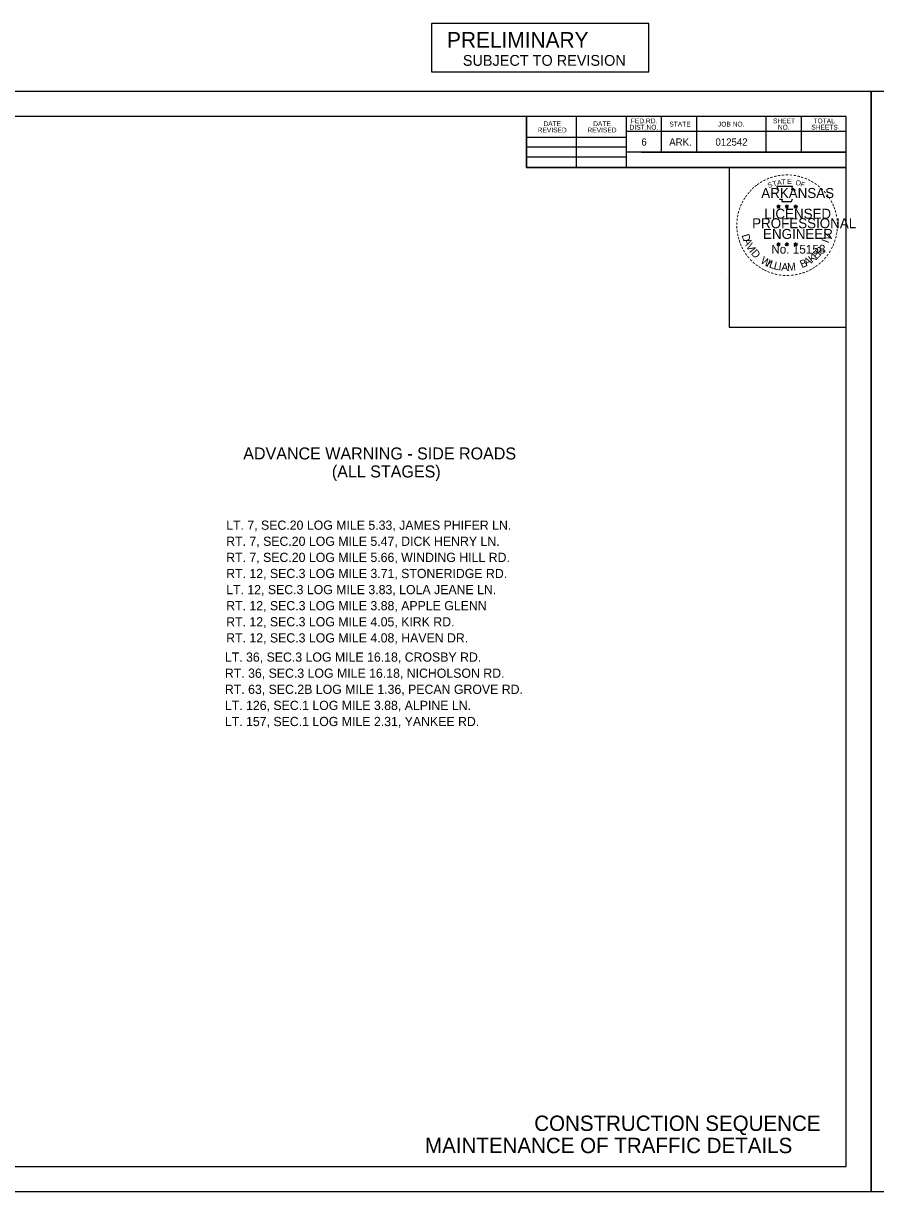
# Model space of a CAD drawing. Extents: x 32485 to 39285, y 55121 to 58033.
# Drawn here: x 33337 to 34190, y 56764 to 57932 of the extents above; entities that cross this region are included whole.
import ezdxf

# ---------------------------------------------------------------- set-up
doc = ezdxf.new("R2010")
doc.units = 0
for name, color, linetype in [('Default', 7, 'Continuous'), ('R_Border Notes', 7, 'Continuous'), ('R_Dimension', 7, 'Continuous'), ('SHET_Annotations', 7, 'Continuous'), ('SHET_Border-Lines', 7, 'Continuous'), ('SHET_Border-Text', 7, 'Continuous'), ('SHET_Stamp-PE-Chief-Eng', 7, 'Continuous'), ('SHET_Stamp-Seal', 7, 'Continuous')]:
    doc.layers.add(name, color=color, linetype=linetype)

msp = doc.modelspace()

# ---------------------------------------------------------------- linework, layer by layer
at = {"layer": 'Default'}
for points in [[(33745.4, 57883.5), (33962.8, 57883.5), (33962.8, 57932), (33745.4, 57932)], [(32485, 57863.9), (32485, 56763.9), (34185, 56763.9), (34185, 57863.9)], [(34185, 57863.9), (34185, 56763.9), (35885, 56763.9), (35885, 57863.9)]]:
    msp.add_lwpolyline(points, close=True, dxfattribs=at)
at = {"layer": 'R_Border Notes'}
for p, q in [((33840.5, 57788), (33840.5, 57838.9)), ((33890.4, 57788), (33890.4, 57838.9)), ((33940.2, 57838.9), (33940.2, 57788)), ((33975.1, 57838.9), (33975.1, 57803.1)), ((34010.5, 57838.9), (34010.5, 57803.1)), ((34079.7, 57838.9), (34079.7, 57803.1)), ((34115.1, 57838.9), (34115.1, 57803.1)), ((34160, 57823.8), (33940.2, 57823.8)), ((34160, 57823.9), (34160, 57823.9)), ((33840.5, 57818.2), (33940.2, 57818.2)), ((33840.5, 57808.6), (33940.2, 57808.6)), ((34160, 57803.1), (33940.2, 57803.1)), ((33955.3, 57803.1), (34160, 57803.1)), ((33840.5, 57798.6), (33940.2, 57798.6)), ((34160, 57788), (33840.5, 57788))]:
    msp.add_line(p, q, dxfattribs=at)
for points in [[(32485, 56763.9), (34185, 56763.9), (34185, 57863.9), (32485, 57863.9)], [(34185, 56763.9), (35885, 56763.9), (35885, 57863.9), (34185, 57863.9)], [(32510, 56788.9), (34160, 56788.9), (34160, 57838.9), (32510, 57838.9)], [(33840.5, 57788), (34160, 57788), (34160, 57838.9), (33840.5, 57838.9)]]:
    msp.add_lwpolyline(points, close=True, dxfattribs=at)
at = {"layer": 'R_Dimension'}
for p, q in [((34090.7, 57749.5), (34092.5, 57748.9)), ((34090.7, 57749.5), (34092, 57749.2)), ((34090.7, 57749.5), (34091.9, 57748.9)), ((34091.4, 57747.4), (34092.5, 57748.9)), ((34091.4, 57747.4), (34092, 57748.7)), ((34091.4, 57747.4), (34092.5, 57748.5)), ((34092.5, 57750.7), (34092.3, 57749.5)), ((34092.5, 57748.9), (34092.5, 57750.7)), ((34092.5, 57750.7), (34092.7, 57749.5)), ((34094.2, 57749.5), (34092.5, 57748.9)), ((34093.5, 57747.4), (34092.5, 57748.9)), ((34093.5, 57747.4), (34092.5, 57748.5)), ((34094.2, 57749.5), (34092.8, 57749.2)), ((34093.5, 57747.4), (34092.8, 57748.9)), ((34094.2, 57749.5), (34093.2, 57749)), ((34099.1, 57749.5), (34100.8, 57748.9)), ((34099.1, 57749.5), (34100.3, 57749.2)), ((34099.1, 57749.5), (34100.3, 57748.9)), ((34099.7, 57747.4), (34100.8, 57748.9)), ((34099.7, 57747.4), (34100.4, 57748.7)), ((34099.7, 57747.4), (34100.8, 57748.5)), ((34100.8, 57750.7), (34100.6, 57749.5)), ((34100.8, 57748.9), (34100.8, 57750.7)), ((34100.8, 57750.7), (34101.1, 57749.5)), ((34102.6, 57749.5), (34100.8, 57748.9)), ((34101.9, 57747.4), (34100.8, 57748.9)), ((34101.9, 57747.4), (34100.8, 57748.5)), ((34102.6, 57749.5), (34101.1, 57749.2)), ((34101.9, 57747.4), (34101.2, 57748.9)), ((34102.6, 57749.5), (34101.5, 57749)), ((34107.9, 57749.4), (34109.6, 57748.9)), ((34107.9, 57749.4), (34109.2, 57749.2)), ((34107.9, 57749.4), (34109.1, 57748.8)), ((34108.6, 57747.4), (34109.6, 57748.9)), ((34108.6, 57747.4), (34109.2, 57748.6)), ((34108.6, 57747.4), (34109.6, 57748.5)), ((34109.6, 57750.7), (34109.4, 57749.4)), ((34109.6, 57748.9), (34109.6, 57750.7)), ((34109.6, 57750.7), (34109.9, 57749.4)), ((34111.4, 57749.4), (34109.6, 57748.9)), ((34110.7, 57747.4), (34109.6, 57748.9)), ((34110.7, 57747.4), (34109.6, 57748.4)), ((34111.4, 57749.4), (34109.9, 57749.2)), ((34110.7, 57747.4), (34110, 57748.8)), ((34111.4, 57749.4), (34110.4, 57748.9)), ((34090.7, 57711.6), (34092.4, 57711.1)), ((34090.7, 57711.6), (34092, 57711.4)), ((34090.7, 57711.6), (34091.9, 57711)), ((34091.4, 57709.6), (34092.4, 57711.1)), ((34091.4, 57709.6), (34092, 57710.8)), ((34091.4, 57709.6), (34092.4, 57710.7)), ((34092.4, 57712.9), (34092.2, 57711.6)), ((34092.4, 57711.1), (34092.4, 57712.9)), ((34092.4, 57712.9), (34092.7, 57711.6)), ((34094.2, 57711.6), (34092.4, 57711.1)), ((34093.5, 57709.6), (34092.4, 57711.1)), ((34093.5, 57709.6), (34092.4, 57710.6)), ((34094.2, 57711.6), (34092.8, 57711.4)), ((34093.5, 57709.6), (34092.8, 57711)), ((34094.2, 57711.6), (34093.2, 57711.1)), ((34099, 57711.6), (34100.8, 57711.1)), ((34099, 57711.6), (34100.3, 57711.4)), ((34099, 57711.6), (34100.2, 57711)), ((34099.7, 57709.6), (34100.8, 57711.1)), ((34099.7, 57709.6), (34100.3, 57710.8)), ((34099.7, 57709.6), (34100.8, 57710.7)), ((34100.8, 57712.9), (34100.6, 57711.6)), ((34100.8, 57711.1), (34100.8, 57712.9)), ((34100.8, 57712.9), (34101, 57711.6)), ((34102.5, 57711.6), (34100.8, 57711.1)), ((34101.9, 57709.6), (34100.8, 57711.1)), ((34101.9, 57709.6), (34100.8, 57710.6)), ((34102.5, 57711.6), (34101.1, 57711.4)), ((34101.9, 57709.6), (34101.2, 57711)), ((34102.5, 57711.6), (34101.5, 57711.1)), ((34107.9, 57711.6), (34109.6, 57711)), ((34107.9, 57711.6), (34109.1, 57711.3)), ((34107.9, 57711.6), (34109.1, 57710.9)), ((34108.5, 57709.5), (34109.6, 57711)), ((34108.5, 57709.5), (34109.2, 57710.7)), ((34108.5, 57709.5), (34109.6, 57710.6)), ((34109.6, 57712.8), (34109.4, 57711.6)), ((34109.6, 57711), (34109.6, 57712.8)), ((34109.6, 57712.8), (34109.9, 57711.6)), ((34111.4, 57711.6), (34109.6, 57711)), ((34110.7, 57709.5), (34109.6, 57711)), ((34110.7, 57709.5), (34109.6, 57710.6)), ((34111.4, 57711.6), (34109.9, 57711.3)), ((34110.7, 57709.5), (34110, 57711)), ((34111.4, 57711.6), (34110.3, 57711))]:
    msp.add_line(p, q, dxfattribs=at)
for points in [[(34090.9, 57768.9), (34092.3, 57764.7)], [(34108.5, 57764.3), (34109.2, 57765.7), (34105.8, 57765.6), (34106.5, 57768.9), (34090.9, 57768.9)], [(34093.4, 57756.7), (34093.4, 57756.3), (34096.2, 57756.2), (34095.9, 57753.9), (34105.3, 57753.9), (34106.3, 57756.5)], [(34092.5, 57750.7), (34093.5, 57747.4), (34090.7, 57749.5), (34094.2, 57749.5), (34091.4, 57747.4), (34092.5, 57750.7)], [(34100.8, 57750.7), (34101.9, 57747.4), (34099.1, 57749.5), (34102.6, 57749.5), (34099.7, 57747.4), (34100.8, 57750.7)], [(34109.6, 57750.7), (34110.7, 57747.4), (34107.9, 57749.4), (34111.4, 57749.4), (34108.6, 57747.4), (34109.6, 57750.7)], [(34092.4, 57712.9), (34093.5, 57709.6), (34090.7, 57711.6), (34094.2, 57711.6), (34091.4, 57709.6), (34092.4, 57712.9)], [(34100.8, 57712.9), (34101.9, 57709.6), (34099, 57711.6), (34102.5, 57711.6), (34099.7, 57709.6), (34100.8, 57712.9)], [(34109.6, 57712.8), (34110.7, 57709.5), (34107.9, 57711.6), (34111.4, 57711.6), (34108.5, 57709.5), (34109.6, 57712.8)]]:
    msp.add_lwpolyline(points, dxfattribs=at)
for centre, radius in [((34092.5, 57748.9), 0.861), ((34092.5, 57748.9), 0.723), ((34092.5, 57748.9), 0.579), ((34092.5, 57748.9), 0.495), ((34092.5, 57748.9), 0.374), ((34092.5, 57748.9), 0.248), ((34092.5, 57748.9), 0.148), ((34100.8, 57748.9), 0.861), ((34100.8, 57748.9), 0.723), ((34100.8, 57748.9), 0.579), ((34100.8, 57748.9), 0.495), ((34100.8, 57748.9), 0.374), ((34100.8, 57748.9), 0.248), ((34100.8, 57748.9), 0.148), ((34109.6, 57748.9), 0.861), ((34109.6, 57748.9), 0.723), ((34109.6, 57748.9), 0.579), ((34109.6, 57748.9), 0.495), ((34109.6, 57748.9), 0.374), ((34109.6, 57748.9), 0.248), ((34109.6, 57748.9), 0.148), ((34092.4, 57711), 0.861), ((34092.4, 57711), 0.723), ((34092.4, 57711), 0.579), ((34092.4, 57711), 0.495), ((34092.4, 57711), 0.374), ((34092.4, 57711), 0.248), ((34092.4, 57711), 0.148), ((34100.8, 57711), 0.861), ((34100.8, 57711), 0.723), ((34100.8, 57711), 0.579), ((34100.8, 57711), 0.495), ((34100.8, 57711), 0.374), ((34100.8, 57711), 0.248), ((34100.8, 57711), 0.148), ((34109.6, 57711), 0.861), ((34109.6, 57711), 0.723), ((34109.6, 57711), 0.579), ((34109.6, 57711), 0.495), ((34109.6, 57711), 0.374), ((34109.6, 57711), 0.248), ((34109.6, 57711), 0.148)]:
    msp.add_circle(centre, radius, dxfattribs=at)
at = {"layer": 'SHET_Border-Text'}
msp.add_lwpolyline([(34043, 57628.2), (34160, 57628.2), (34160, 57788), (34043, 57788)], close=True, dxfattribs=at)
at = {"layer": 'SHET_Stamp-PE-Chief-Eng'}
msp.add_line((34040.5, 57675.9), (34040.5, 57675.9), dxfattribs=at)
at = {"layer": 'SHET_Stamp-Seal'}
msp.add_lwpolyline([(34050, 57787.9), (34050.2, 57787.9), (34050.2, 57788), (34050, 57788)], close=True, dxfattribs=at)

# ---------------------------------------------------------------- texts
at = {"layer": 'Default'}
for s, height, p in [('PRELIMINARY', 15.6, (33761, 57907.8)), ('SUBJECT TO REVISION', 10.8, (33776.8, 57889.6)), ('ADVANCE WARNING - SIDE ROADS', 12, (33557.2, 57496)), ('(ALL STAGES)', 12, (33645.8, 57478)), ('LT. 7, SEC.20 LOG MILE 5.33, JAMES PHIFER LN.', 9.2, (33540.1, 57425.7)), ('RT. 7, SEC.20 LOG MILE 5.47, DICK HENRY LN.', 9.2, (33540.1, 57409.6)), ('RT. 7, SEC.20 LOG MILE 5.66, WINDING HILL RD.', 9.2, (33540.1, 57393.5)), ('RT. 12, SEC.3 LOG MILE 3.71, STONERIDGE RD.', 9.2, (33540.1, 57377.4)), ('LT. 12, SEC.3 LOG MILE 3.83, LOLA JEANE LN.', 9.2, (33540.1, 57361.3)), ('RT. 12, SEC.3 LOG MILE 3.88, APPLE GLENN', 9.2, (33540.1, 57345.2)), ('RT. 12, SEC.3 LOG MILE 4.05, KIRK RD.', 9.2, (33540.1, 57329.1)), ('RT. 12, SEC.3 LOG MILE 4.08, HAVEN DR.', 9.2, (33540.1, 57313)), ('LT. 36, SEC.3 LOG MILE 16.18, CROSBY RD.', 9.2, (33538.8, 57293.8)), ('RT. 36, SEC.3 LOG MILE 16.18, NICHOLSON RD.', 9.2, (33538.8, 57277.7)), ('RT. 63, SEC.2B LOG MILE 1.36, PECAN GROVE RD.', 9.2, (33538.8, 57261.6)), ('LT. 126, SEC.1 LOG MILE 3.88, ALPINE LN.', 9.2, (33538.8, 57245.5)), ('LT. 157, SEC.1 LOG MILE 2.31, YANKEE RD.', 9.2, (33538.8, 57229.4)), ('CONSTRUCTION SEQUENCE', 15.349, (33848.2, 56824.6)), ('MAINTENANCE OF TRAFFIC DETAILS', 15.349, (33739, 56802.4))]:
    msp.add_text(s, height=height, dxfattribs=at).set_placement(p)
at = {"layer": 'R_Dimension'}
for s, height, rotation, p in [('-', 8, 28.7918, (34078.3, 57771.6)), ('-', 8, 24.3072, (34081.5, 57773.2)), ('-', 8, 19.1761, (34084.7, 57774.5)), ('-', 8, 13.6302, (34088.4, 57775.7)), ('-', 8, 10.2193, (34091.8, 57776.5)), ('T', 5, 6.0228, (34095.6, 57771)), ('-', 8, 5.8968, (34095.5, 57777.1)), ('-', 8, 0.1862, (34099.3, 57777.4)), ('E', 5, 0.8323, (34101.2, 57771.5)), ('-', 8, 357.743, (34102.9, 57777.4)), ('-', 8, 352.1617, (34106.6, 57777.1)), ('-', 8, 347.2049, (34110.2, 57776.5)), ('-', 8, 342.3362, (34113.4, 57775.7)), ('-', 8, 337.8551, (34117.1, 57774.6)), ('-', 8, 334.1211, (34120.2, 57773.3)), ('-', 8, 48.4231, (34065.7, 57761.4)), ('-', 8, 42.9622, (34067.9, 57763.8)), ('-', 8, 38.9507, (34070.1, 57765.9)), ('-', 8, 36.2317, (34072.5, 57767.7)), ('-', 8, 34.0636, (34075.3, 57769.7)), ('S', 5, 21.594, (34082.7, 57767.3)), ('T', 5, 16.4036, (34087.3, 57768.9)), ('A', 5, 11.2132, (34091.4, 57770.2)), ('O', 5, 350.4515, (34109.2, 57770.5)), ('F', 5, 340.0707, (34114, 57769.4)), ('-', 8, 329.6409, (34123.1, 57771.8)), ('-', 8, 325.8627, (34126.4, 57770)), ('-', 8, 320.5297, (34129.4, 57767.9)), ('-', 8, 315.5786, (34132.4, 57765.5)), ('-', 8, 309.8797, (34135.2, 57762.7)), ('-', 8, 62.8713, (34058.4, 57750.4)), ('-', 8, 58.0706, (34060, 57753.5)), ('-', 8, 54.2325, (34061.6, 57756.1)), ('-', 8, 50.6142, (34063.7, 57758.9)), ('-', 8, 306.6522, (34137.9, 57759.7)), ('-', 7, 303.6753, (34140.3, 57756.9)), ('-', 8, 299.6684, (34141.9, 57753.8)), ('-', 8, 75.461, (34055, 57740.6)), ('-', 8, 72.3945, (34056, 57744.2)), ('-', 8, 67.7743, (34057.1, 57747.4)), ('-', 8, 294.6628, (34143.5, 57750.8)), ('-', 8, 290.5728, (34144.8, 57747.9)), ('-', 8, 285.1233, (34146, 57745)), ('-', 8, 280.5493, (34147, 57741.3)), ('-', 8, 89.0622, (34053.9, 57730.1)), ('-', 8, 94.1959, (34054, 57726.5)), ('-', 8, 85.1863, (34054, 57733.6)), ('-', 8, 81.2013, (34054.4, 57737.1)), ('-', 8, 276.5962, (34147.8, 57737.4)), ('-', 8, 274.3301, (34148.1, 57733.8)), ('-', 8, 269.9407, (34148.3, 57730.7)), ('-', 8, 98.9479, (34054.4, 57723.1)), ('-', 8, 101.7149, (34055.1, 57719.5)), ('-', 8, 105.4578, (34055.9, 57716.5)), ('D', 7.7, 286.2848, (34055.5, 57720.2)), ('V', 7.7, 72.6573, (34143.5, 57714.4)), ('-', 8, 255.7626, (34147.3, 57720.7)), ('-', 8, 260.9953, (34147.8, 57724.1)), ('-', 8, 263.5172, (34148.2, 57727.3)), ('-', 8, 109.0874, (34057, 57713.4)), ('-', 8, 114.0643, (34058.2, 57710.4)), ('-', 8, 115.7289, (34059.8, 57707.3)), ('A', 7.7, 292.7835, (34057, 57715.2)), ('V', 7.7, 300.7936, (34059.5, 57709.3)), ('I', 7.7, 308.3502, (34062.7, 57704.1)), ('D', 7.7, 311.9774, (34064.5, 57701.8)), ('R', 7.7, 50.3651, (34134.1, 57699.2)), ('I', 7.7, 69.0301, (34142.4, 57711.7)), (',', 7.7, 57.4684, (34137.7, 57703.6)), ('-', 8, 244.6197, (34143.9, 57710.6)), ('-', 8, 247.8887, (34145.2, 57713.7)), ('-', 8, 252.8681, (34146.3, 57717.1)), ('-', 8, 120.4471, (34061.5, 57704.4)), ('-', 8, 125.8934, (34063.6, 57701.5)), ('-', 8, 130.7181, (34065.9, 57698.8)), ('-', 8, 134.2238, (34068.4, 57696.1)), ('W', 7.7, 328.0731, (34073.8, 57692.9)), ('I', 7.7, 336.6877, (34079.8, 57689.4)), ('L', 7.7, 340.3149, (34082.4, 57688.2)), ('B', 7.7, 22.8589, (34115.8, 57687.2)), ('A', 7.7, 28.9042, (34120.3, 57689.1)), ('K', 7.7, 36.9143, (34125.9, 57692.2)), ('E', 7.7, 44.0175, (34130.4, 57695.7)), ('-', 8, 225.7653, (34135.4, 57697.9)), ('-', 8, 231.2538, (34137.8, 57700.7)), ('-', 8, 233.8452, (34139.9, 57703.5)), ('-', 8, 239.0712, (34142, 57706.8)), ('-', 8, 138.9338, (34071.1, 57693.7)), ('-', 8, 144.6463, (34073.9, 57691.7)), ('-', 8, 148.0898, (34076.7, 57689.9)), ('-', 8, 151.5704, (34079.6, 57688.2)), ('-', 8, 154.6002, (34082.2, 57687)), ('-', 8, 158.5612, (34085.3, 57685.7)), ('-', 8, 162.7983, (34088.7, 57684.7)), ('L', 7.7, 346.6625, (34087.2, 57686.4)), ('I', 7.7, 353.0101, (34092.2, 57685.2)), ('A', 7.7, 356.6373, (34095.1, 57684.8)), ('M', 7.7, 4.6473, (34101.5, 57684.5)), ('-', 8, 199.4643, (34118.3, 57686.3)), ('-', 8, 204.2516, (34121.5, 57687.7)), ('-', 8, 207.3568, (34124.6, 57689.3)), ('-', 8, 212.2491, (34127.4, 57691.1)), ('-', 8, 215.7363, (34130, 57693)), ('-', 8, 221.0851, (34132.8, 57695.4)), ('-', 8, 167.5555, (34092.3, 57683.8)), ('-', 8, 173.1155, (34096.2, 57683.3)), ('-', 8, 176.5183, (34099.9, 57683)), ('-', 8, 181.5918, (34103.6, 57683.1)), ('-', 8, 185.8167, (34107.7, 57683.5)), ('-', 8, 191.2858, (34111.3, 57684.2)), ('-', 8, 195.4743, (34115, 57685.2))]:
    msp.add_text(s, height=height, rotation=rotation, dxfattribs=at).set_placement(p)
for s, height, p in [('ARKANSAS', 10, (34075.2, 57757.4)), ('LICENSED', 10, (34078.2, 57736.7)), ('PROFESSIONAL', 10, (34066.1, 57727.2)), ('ENGINEER', 10, (34077, 57716.5)), ('No. 15158', 8.78, (34085.2, 57701.8)), ('AAMU', 0.0001, (34100.5, 57684.5))]:
    msp.add_text(s, height=height, dxfattribs=at).set_placement(p)
at = {"layer": 'SHET_Annotations'}
for s, p in [('FED.RD.', (33944.8, 57832.1)), ('SHEET', (34087, 57832.1)), ('TOTAL', (34127.4, 57832.1)), ('REVISED', (33851.6, 57823)), ('DATE', (33857.3, 57829.3)), ('REVISED', (33901.4, 57823)), ('DATE', (33907.1, 57829.3)), ('DIST.NO.', (33943.5, 57825.8)), ('STATE', (33983.3, 57828.9)), ('JOB NO.', (34031.9, 57828.9)), ('NO.', (34091.8, 57825.8)), ('SHEETS', (34125.2, 57825.8))]:
    msp.add_text(s, height=4.8, dxfattribs=at).set_placement(p)
at = {"layer": 'SHET_Border-Lines'}
for s, p in [('6', (33955.3, 57809.8)), ('ARK.', (33983.2, 57809.8)), ('012542', (34029.4, 57809.8))]:
    msp.add_text(s, height=7.2, dxfattribs=at).set_placement(p)
at = {"layer": 'SHET_Stamp-Seal'}
for s, height in [('PRELIMINARY', 0.013), ('SUBJECT TO REVISION', 0.009)]:
    msp.add_text(s, height=height, dxfattribs=at).set_placement((34050, 57787.9))

doc.saveas('drawing.dxf')
